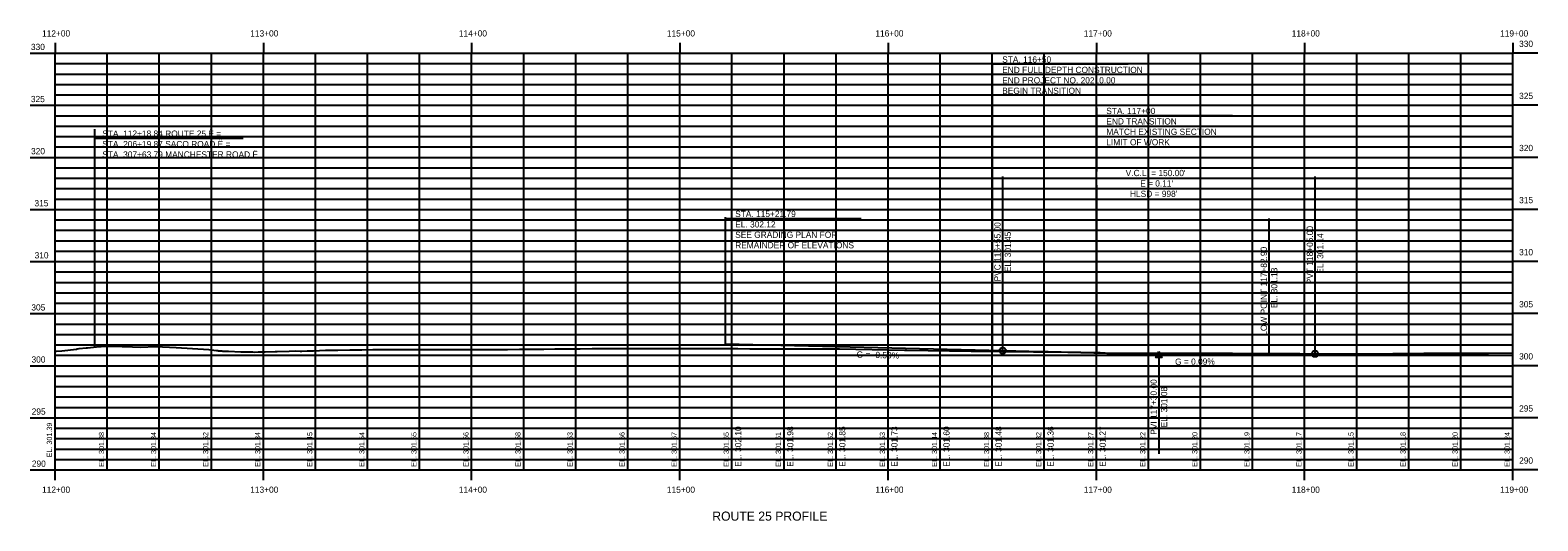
# Model space of a CAD drawing. Extents: x 916064 to 2216531, y 210276 to 327856.
# Drawn here: x 917597 to 918321, y 327621 to 327856 of the extents above; entities that cross this region are included whole.
import ezdxf

# ---------------------------------------------------------------- set-up
doc = ezdxf.new("R2010")
doc.units = 0
for name, color, linetype in [('ANNOTATION', 7, 'Continuous'), ('BARRIER', 7, 'Continuous'), ('D_Roadway_Centerline', 7, 'Continuous'), ('D_Roadway_Centerline_Bearings', 7, 'Continuous'), ('D_Roadway_Centerline_CurveData', 7, 'Continuous'), ('D_Roadway_Centerline_Flags', 7, 'Continuous'), ('D_Roadway_Centerline_Text', 7, 'Continuous'), ('D_Roadway_Edge_Pavement', 7, 'Continuous')]:
    doc.layers.add(name, color=color, linetype=linetype)

msp = doc.modelspace()

# ---------------------------------------------------------------- linework, layer by layer
at = {"layer": 'ANNOTATION'}
msp.add_line((917930.3, 327706), (918063.51, 327702.67), dxfattribs=at)
msp.add_lwpolyline([(918063.51, 327702.67), (918066.63, 327702.6), (918069.76, 327702.52), (918072.88, 327702.45), (918076.01, 327702.38), (918079.13, 327702.31), (918082.26, 327702.24), (918085.38, 327702.17), (918088.51, 327702.11), (918091.63, 327702.05), (918094.76, 327701.99), (918097.88, 327701.93), (918101.01, 327701.87), (918104.13, 327701.82), (918107.26, 327701.77), (918108.51, 327701.75)], dxfattribs=at)
at = {"layer": 'D_Roadway_Centerline'}
for p, q in [((917608.51, 327850.41), (917608.51, 327845.41)), ((917708.51, 327850.41), (917708.51, 327845.41)), ((917808.51, 327850.41), (917808.51, 327845.41)), ((917908.51, 327850.41), (917908.51, 327845.41)), ((918008.51, 327850.41), (918008.51, 327845.41)), ((918108.51, 327850.41), (918108.51, 327845.41)), ((918208.51, 327850.41), (918208.51, 327845.41)), ((918308.51, 327850.41), (918308.51, 327845.41)), ((917596.51, 327845.41), (917608.51, 327845.41)), ((917596.51, 327845.41), (917608.51, 327845.41)), ((917608.51, 327845.41), (918308.51, 327845.41)), ((917608.51, 327645.41), (917608.51, 327845.41)), ((917708.51, 327645.41), (917708.51, 327845.41)), ((917808.51, 327645.41), (917808.51, 327845.41)), ((917908.51, 327645.41), (917908.51, 327845.41)), ((918008.51, 327645.41), (918008.51, 327845.41)), ((918108.51, 327645.41), (918108.51, 327845.41)), ((918208.51, 327645.41), (918208.51, 327845.41)), ((918308.51, 327645.41), (918308.51, 327845.41)), ((918320.51, 327845.41), (918308.51, 327845.41)), ((918320.51, 327845.41), (918308.51, 327845.41)), ((917596.51, 327820.41), (917608.51, 327820.41)), ((917608.51, 327820.41), (918308.51, 327820.41)), ((918320.51, 327820.41), (918308.51, 327820.41)), ((917596.51, 327795.41), (917608.51, 327795.41)), ((917608.51, 327795.41), (918308.51, 327795.41)), ((918320.51, 327795.41), (918308.51, 327795.41)), ((917596.51, 327770.41), (917608.51, 327770.41)), ((917608.51, 327770.41), (918308.51, 327770.41)), ((918320.51, 327770.41), (918308.51, 327770.41)), ((917596.51, 327745.41), (917608.51, 327745.41)), ((917608.51, 327745.41), (918308.51, 327745.41)), ((918320.51, 327745.41), (918308.51, 327745.41)), ((917596.51, 327720.41), (917608.51, 327720.41)), ((917608.51, 327720.41), (918308.51, 327720.41)), ((918320.51, 327720.41), (918308.51, 327720.41)), ((917596.51, 327695.41), (917608.51, 327695.41)), ((917608.51, 327695.41), (918308.51, 327695.41)), ((918320.51, 327695.41), (918308.51, 327695.41)), ((917596.51, 327670.41), (917608.51, 327670.41)), ((917608.51, 327670.41), (918308.51, 327670.41)), ((918320.51, 327670.41), (918308.51, 327670.41)), ((917596.51, 327645.41), (917608.51, 327645.41)), ((917608.51, 327645.41), (918308.51, 327645.41)), ((917608.51, 327640.42), (917608.51, 327645.41)), ((917708.51, 327640.42), (917708.51, 327645.41)), ((917808.51, 327640.42), (917808.51, 327645.41)), ((917908.51, 327640.42), (917908.51, 327645.41)), ((918008.51, 327640.42), (918008.51, 327645.41)), ((918108.51, 327640.42), (918108.51, 327645.41)), ((918208.51, 327640.42), (918208.51, 327645.41)), ((918320.51, 327645.41), (918308.51, 327645.41)), ((918308.51, 327640.42), (918308.51, 327645.41))]:
    msp.add_line(p, q, dxfattribs=at)
at = {"layer": 'D_Roadway_Centerline_Bearings'}
for p, q in [((918063.51, 327702.67), (918063.51, 327786.19)), ((918213.51, 327701.26), (918213.51, 327786.19)), ((918063.51, 327727.67), (918063.51, 327775.27)), ((918213.51, 327726.12), (918213.51, 327773.72)), ((918191.41, 327701.07), (918191.41, 327766.07)), ((918063.51, 327702.67), (918063.51, 327727.67)), ((918213.51, 327701.26), (918213.51, 327726.12)), ((918101.01, 327701.74), (918138.51, 327700.8)), ((918138.51, 327700.8), (918176.01, 327700.96)), ((918138.51, 327700.8), (918138.51, 327653.2))]:
    msp.add_line(p, q, dxfattribs=at)
msp.add_lwpolyline([(918063.51, 327785.41), (918213.51, 327785.41)], dxfattribs=at)
msp.add_lwpolyline([(918138.51, 327702.3), (918140.01, 327699.3), (918137.01, 327699.3)], close=True, dxfattribs=at)
for centre in [(918063.51, 327702.67), (918213.51, 327701.12)]:
    msp.add_circle(centre, 1.5, dxfattribs=at)
at = {"layer": 'D_Roadway_Centerline_Flags'}
msp.add_lwpolyline([(917608.51, 327702.34), (917609.2, 327702.35), (917611.69, 327702.63), (917618.84, 327703.44), (917619.16, 327703.5), (917620.02, 327703.67), (917623.47, 327703.93), (917624.12, 327703.98), (917628.33, 327704.44), (917629.73, 327704.58), (917630.65, 327704.71), (917632.65, 327704.77), (917633.94, 327704.82), (917635.66, 327704.86), (917645.63, 327704.46), (917649.34, 327704.34), (917656.87, 327704.7), (917666.56, 327704.17), (917682.24, 327703.14), (917686.01, 327702.74), (917686.4, 327702.69), (917686.7, 327702.65), (917686.98, 327702.62), (917687.2, 327702.6), (917687.77, 327702.55), (917688.53, 327702.5), (917689.01, 327702.47), (917691.83, 327702.37), (917697.65, 327702.16), (917700.65, 327702.05), (917703.47, 327702.02), (917704.4, 327702), (917706.04, 327702.04), (917709.29, 327702.14), (917714.13, 327702.29), (917715.11, 327702.32), (917720.93, 327702.46), (917723.91, 327702.53), (917726.15, 327702.43), (917726.39, 327702.42), (917726.75, 327702.43), (917726.91, 327702.43), (917729.59, 327702.55), (917732.57, 327702.64), (917738.39, 327702.82), (917739.26, 327702.84), (917744.21, 327702.92), (917750.03, 327703.01), (917755.85, 327703.08), (917761.03, 327703.13), (917761.67, 327703.13), (917767.49, 327703.17), (917769.87, 327703.18), (917773.31, 327703.19), (917779.13, 327703.19), (917784.95, 327703.17), (917790.76, 327703.14), (917792.33, 327703.13), (917796.58, 327703.16), (917802.4, 327703.18), (917808.22, 327703.19), (917811.23, 327703.19), (917814.04, 327703.19), (917819.86, 327703.19), (917822.09, 327703.18), (917825.68, 327703.24), (917831.5, 327703.31), (917837.32, 327703.37), (917843.14, 327703.42), (917848.44, 327703.45), (917848.96, 327703.46), (917852.46, 327703.47), (917854.78, 327703.51), (917855.64, 327703.53), (917860.6, 327703.58), (917866.42, 327703.63), (917872.24, 327703.67), (917878.06, 327703.7), (917878.77, 327703.7), (917883.88, 327703.7), (917885.06, 327703.69), (917885.6, 327703.69), (917889.7, 327703.72), (917895.52, 327703.74), (917901.34, 327703.75), (917907.16, 327703.76), (917912.98, 327703.76), (917915.8, 327703.75), (917918.74, 327703.74), (917918.8, 327703.74), (917921.77, 327703.71), (917924.62, 327703.7), (917930.44, 327703.67), (917936.26, 327703.64), (917942.08, 327703.59), (917947.9, 327703.54), (917951.25, 327703.5), (917953.72, 327703.48), (917953.85, 327703.47), (917959.54, 327703.49), (917983.61, 327703.53), (917985.08, 327703.48), (918016.32, 327702.93), (918017.3, 327702.92), (918048.45, 327702.37), (918078.34, 327702.13), (918079.83, 327702.07), (918110.37, 327701.72), (918111.6, 327701.67), (918112.81, 327701.64), (918142.89, 327701.45), (918143.77, 327701.44), (918173.89, 327701.39), (918205.44, 327701.3), (918206.17, 327701.29), (918235.59, 327701.15), (918235.79, 327701.15), (918265.68, 327701.37), (918265.69, 327701.37), (918296.83, 327701.43), (918308.51, 327701.6)], dxfattribs=at)
at = {"layer": 'D_Roadway_Centerline_Text'}
for p, q in [((917633.51, 327645.41), (917633.51, 327845.41)), ((917658.51, 327645.41), (917658.51, 327845.41)), ((917683.51, 327645.41), (917683.51, 327845.41)), ((917733.51, 327645.41), (917733.51, 327845.41)), ((917758.51, 327645.41), (917758.51, 327845.41)), ((917783.51, 327645.41), (917783.51, 327845.41)), ((917833.51, 327645.41), (917833.51, 327845.41)), ((917858.51, 327645.41), (917858.51, 327845.41)), ((917883.51, 327645.41), (917883.51, 327845.41)), ((917933.51, 327645.41), (917933.51, 327845.41)), ((917958.51, 327645.41), (917958.51, 327845.41)), ((917983.51, 327645.41), (917983.51, 327845.41)), ((918033.51, 327645.41), (918033.51, 327845.41)), ((918058.51, 327645.41), (918058.51, 327845.41)), ((918083.51, 327645.41), (918083.51, 327845.41)), ((918133.51, 327645.41), (918133.51, 327845.41)), ((918158.51, 327645.41), (918158.51, 327845.41)), ((918183.51, 327645.41), (918183.51, 327845.41)), ((918233.51, 327645.41), (918233.51, 327845.41)), ((918258.51, 327645.41), (918258.51, 327845.41)), ((918283.51, 327645.41), (918283.51, 327845.41)), ((917608.51, 327840.41), (918308.51, 327840.41)), ((917608.51, 327835.41), (918308.51, 327835.41)), ((917608.51, 327830.41), (918308.51, 327830.41)), ((917608.51, 327825.41), (918308.51, 327825.41)), ((917608.51, 327815.41), (918308.51, 327815.41)), ((917608.51, 327810.41), (918308.51, 327810.41)), ((917608.51, 327805.41), (918308.51, 327805.41)), ((917608.51, 327800.41), (918308.51, 327800.41)), ((917608.51, 327790.41), (918308.51, 327790.41)), ((917608.51, 327785.41), (918308.51, 327785.41)), ((917608.51, 327780.41), (918308.51, 327780.41)), ((917608.51, 327775.41), (918308.51, 327775.41)), ((917608.51, 327765.41), (918308.51, 327765.41)), ((917608.51, 327760.41), (918308.51, 327760.41)), ((917608.51, 327755.41), (918308.51, 327755.41)), ((917608.51, 327750.41), (918308.51, 327750.41)), ((917608.51, 327740.41), (918308.51, 327740.41)), ((917608.51, 327735.41), (918308.51, 327735.41)), ((917608.51, 327730.41), (918308.51, 327730.41)), ((917608.51, 327725.41), (918308.51, 327725.41)), ((917608.51, 327715.41), (918308.51, 327715.41)), ((917608.51, 327710.41), (918308.51, 327710.41)), ((917608.51, 327705.41), (918308.51, 327705.41)), ((917608.51, 327700.41), (918308.51, 327700.41)), ((917608.51, 327690.41), (918308.51, 327690.41)), ((917608.51, 327685.41), (918308.51, 327685.41)), ((917608.51, 327680.41), (918308.51, 327680.41)), ((917608.51, 327675.41), (918308.51, 327675.41)), ((917608.51, 327665.41), (918308.51, 327665.41)), ((917608.51, 327660.41), (918308.51, 327660.41)), ((917608.51, 327655.41), (918308.51, 327655.41)), ((917608.51, 327650.41), (918308.51, 327650.41))]:
    msp.add_line(p, q, dxfattribs=at)
at = {"layer": 'D_Roadway_Edge_Pavement'}
for p, q in [((918058.51, 327840.86), (918058.51, 327702.49)), ((918123.85, 327840.11), (918058.51, 327840.11)), ((918108.51, 327819.18), (918108.51, 327788.68)), ((918173.85, 327815.4), (918108.51, 327815.4)), ((917627.35, 327808.92), (917627.35, 327704.33)), ((917698.8, 327804.52), (917627.35, 327804.52)), ((918108.51, 327782.14), (918108.51, 327701.75)), ((917930.3, 327766.73), (917930.3, 327706)), ((917995.64, 327765.98), (917930.3, 327765.98))]:
    msp.add_line(p, q, dxfattribs=at)

# ---------------------------------------------------------------- texts
at = {"layer": 'ANNOTATION'}
for s, p in [('LOW POINT 117+82.90', (918190.41, 327709.8)), ('EL. 301.13', (918195.41, 327723.05))]:
    msp.add_text(s, height=3, rotation=90, dxfattribs=at).set_placement(p)
at = {"layer": 'BARRIER'}
for s, p in [('EL. 302.10', (917938.01, 327646.91)), ('EL. 301.98', (917963.01, 327646.91)), ('EL. 301.85', (917988.01, 327646.91)), ('EL. 301.73', (918013.01, 327646.91)), ('EL. 301.60', (918038.01, 327646.91)), ('EL. 301.48', (918063.01, 327646.91)), ('EL. 301.36', (918088.01, 327646.91)), ('EL. 301.27', (918113.01, 327646.91))]:
    msp.add_text(s, height=3, rotation=90, dxfattribs=at).set_placement(p)
at = {"layer": 'D_Roadway_Centerline_Bearings'}
for s, p in [("V.C.L. = 150.00'", (918122.58, 327786.41)), ("E = 0.11'", (918129.53, 327781.41)), ("HLSD = 998'", (918124.65, 327776.41))]:
    msp.add_text(s, height=3, dxfattribs=at).set_placement(p)
for s, rotation, p in [('PVC 116+55.00', 90, (918062.51, 327735.87)), ('PVT 118+05.00', 90, (918212.51, 327734.49)), ('EL. 301.45', 90, (918067.51, 327740.33)), ('EL. 301.14', 90, (918217.51, 327739.57)), (' G = -0.50%', 358.5679, (917992.23, 327699.36)), ('G = 0.09%', 0.24749, (918146.31, 327695.84)), ('PVI 117+30.00', 90, (918137.51, 327662.27)), ('EL. 301.08', 90, (918142.51, 327665.86))]:
    msp.add_text(s, height=3, rotation=rotation, dxfattribs=at).set_placement(p)
at = {"layer": 'D_Roadway_Centerline_CurveData'}
for s, height, p in [('112+00', 3, (917602.22, 327853.41)), ('113+00', 3, (917702.19, 327853.41)), ('114+00', 3, (917802.38, 327853.41)), ('115+00', 3, (917902.27, 327853.41)), ('116+00', 3, (918002.38, 327853.41)), ('117+00', 3, (918102.46, 327853.41)), ('118+00', 3, (918202.32, 327853.41)), ('119+00', 3, (918302.38, 327853.41)), ('330', 3, (917596.89, 327846.91)), ('330', 3, (917596.89, 327846.91)), ('330', 3, (918311.51, 327848.41)), ('330', 3, (918311.51, 327848.41)), ('325', 3, (917596.86, 327821.91)), ('325', 3, (918311.51, 327823.41)), ('320', 3, (917596.94, 327796.91)), ('320', 3, (918311.51, 327798.41)), ('315', 3, (917598.57, 327771.91)), ('315', 3, (918311.51, 327773.41)), ('310', 3, (917598.65, 327746.91)), ('310', 3, (918311.51, 327748.41)), ('305', 3, (918311.51, 327723.41)), ('305', 3, (917597.08, 327721.91)), ('300', 3, (917597.16, 327696.91)), ('300', 3, (918311.51, 327698.41)), ('295', 3, (918311.51, 327673.41)), ('295', 3, (917597.24, 327671.91)), ('290', 3, (917597.32, 327646.91)), ('290', 3, (918311.51, 327648.41)), ('112+00', 3, (917602.22, 327634.42)), ('113+00', 3, (917702.19, 327634.42)), ('114+00', 3, (917802.38, 327634.42)), ('115+00', 3, (917902.27, 327634.42)), ('116+00', 3, (918002.38, 327634.42)), ('117+00', 3, (918102.46, 327634.42)), ('118+00', 3, (918202.32, 327634.42)), ('119+00', 3, (918302.38, 327634.42)), ('ROUTE 25 PROFILE', 4.3749, (917924.06, 327621.04))]:
    msp.add_text(s, height=height, dxfattribs=at).set_placement(p)
at = {"layer": 'D_Roadway_Edge_Pavement'}
for s, p in [('STA. 116+50', (918063.27, 327840.89)), ('END FULL DEPTH CONSTRUCTION', (918063.27, 327835.89)), ('END PROJECT NO. 20210.00', (918063.27, 327830.89)), ('BEGIN TRANSITION', (918063.27, 327825.89)), ('STA. 117+00', (918113.27, 327816.18)), ('END TRANSITION', (918113.27, 327811.18)), ('STA. 112+18.84 ROUTE 25 Ë =', (917631.13, 327805.29)), ('MATCH EXISTING SECTION', (918113.27, 327806.18)), ('STA. 206+19.87 SACO ROAD Ë =', (917631.13, 327800.29)), ('STA. 307+63.79 MANCHESTER ROAD Ë', (917631.13, 327795.29)), ('LIMIT OF WORK', (918113.27, 327801.18)), ('STA. 115+21.79', (917935.06, 327766.76)), ('EL. 302.12', (917935.06, 327761.76)), ('SEE GRADING PLAN FOR', (917935.06, 327756.76)), ('REMAINDER OF ELEVATIONS', (917935.06, 327751.76))]:
    msp.add_text(s, height=3, dxfattribs=at).set_placement(p)
for s, p in [('EL. 301.39', (917607.01, 327651.43)), ('EL. 301.88', (917632.01, 327646.91)), ('EL. 301.84', (917657.01, 327646.91)), ('EL. 301.52', (917682.01, 327646.91)), ('EL. 301.34', (917707.01, 327646.91)), ('EL. 301.45', (917732.01, 327646.91)), ('EL. 301.54', (917757.01, 327646.91)), ('EL. 301.55', (917782.01, 327646.91)), ('EL. 301.56', (917807.01, 327646.91)), ('EL. 301.58', (917832.01, 327646.91)), ('EL. 301.63', (917857.01, 327646.91)), ('EL. 301.66', (917882.01, 327646.91)), ('EL. 301.67', (917907.01, 327646.91)), ('EL. 301.65', (917932.01, 327646.91)), ('EL. 301.61', (917957.01, 327646.91)), ('EL. 301.62', (917982.01, 327646.91)), ('EL. 301.53', (918007.01, 327646.91)), ('EL. 301.44', (918032.01, 327646.91)), ('EL. 301.38', (918057.01, 327646.91)), ('EL. 301.32', (918082.01, 327646.91)), ('EL. 301.27', (918107.01, 327646.91)), ('EL. 301.22', (918132.01, 327646.91)), ('EL. 301.20', (918157.01, 327646.91)), ('EL. 301.19', (918182.01, 327646.91)), ('EL. 301.17', (918207.01, 327646.91)), ('EL. 301.15', (918232.01, 327646.91)), ('EL. 301.18', (918257.01, 327646.91)), ('EL. 301.20', (918282.01, 327646.91)), ('EL. 301.24', (918307.01, 327646.91))]:
    msp.add_text(s, height=2.5, rotation=90, dxfattribs=at).set_placement(p)

doc.saveas('drawing.dxf')
